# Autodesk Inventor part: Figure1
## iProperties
Shininess: 77.0
Angle Display Precision: 2
Document Length Units: 11269
Document Angle Units: 11279
Document Time Units: 11290
Document Mass Units: 11283
Document Length Units Precision: 3
Document Angle Units Precision: 2
Created: 2001-12
Part Number: Figure1
Document SubType Name: Modeling
Designer: Renu Muthoo
Density: 1 g/cm^3
Density: 0.0
Volumn: 0.0
Area: 0.0
PropertySet Name: Model Information
Control State: 0
Master: False
Checked Out: False
Author: Renu Muthoo
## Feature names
1. Extrusion1
2. Extrusion8
